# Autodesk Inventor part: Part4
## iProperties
Shininess: 64.0
Length Units: 11269
Angle Units: 11279
Time Units: 11290
Mass Units: 11283
Length Display Precision: 3
Angle Display Precision: 2
Compacted: True
Part Number: Part4
Document SubType Name: Modeling
Created: 2002-12
Designer: deepak
Density: 1 g/cm^3
Density: 0.0
Volumn: 0.0
Area: 0.0
PropertySet Name: Model Information
Control State: 0
Master: False
Checked Out: False
Author: deepak
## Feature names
1. Extrusion1
2. Split1
